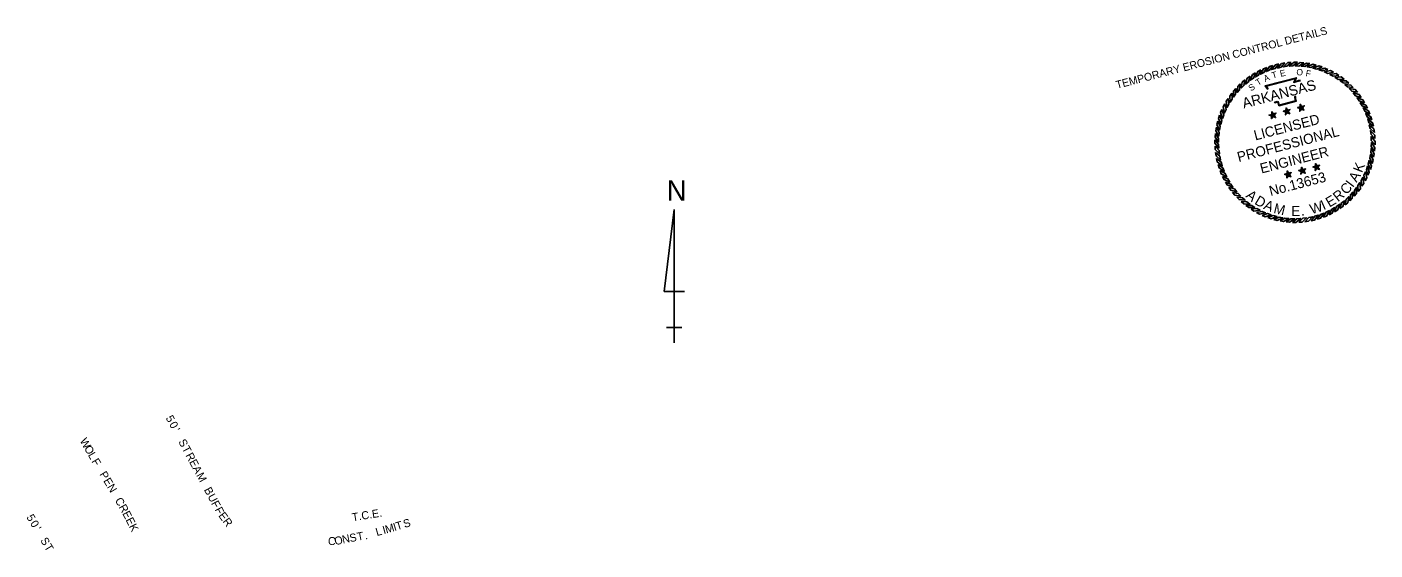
# Model space of a CAD drawing. Extents: x 830993 to 836451, y 495580 to 497751.
# Drawn here: x 835245 to 836255, y 496986 to 497378 of the extents above; entities that cross this region are included whole.
import ezdxf

# ---------------------------------------------------------------- set-up
doc = ezdxf.new("R2010")
doc.units = 0
for name, color, linetype in [('1', 7, 'Continuous'), ('8', 7, 'Continuous'), ('G-ANNO-STMP-AEW', 7, 'Continuous'), ('G-ANNO-TEXT', 7, 'Continuous'), ('Level 1', 7, 'Continuous'), ('R_Draft', 7, 'Continuous')]:
    doc.layers.add(name, color=color, linetype=linetype)

msp = doc.modelspace()

# ---------------------------------------------------------------- linework, layer by layer
at = {"layer": 'G-ANNO-STMP-AEW'}
for points in [[(836173.7, 497347.8), (836171.3, 497346.9), (836169.1, 497342.8), (836171.6, 497344)], [(836178.2, 497349.3), (836175.7, 497348.6), (836173.2, 497344.7), (836175.8, 497345.7)], [(836182.7, 497350.5), (836180.2, 497349.9), (836177.4, 497346.2), (836180.1, 497347)], [(836187.4, 497351.2), (836184.8, 497350.9), (836181.8, 497347.4), (836184.5, 497348)], [(836192.1, 497351.6), (836189.5, 497351.5), (836186.2, 497348.3), (836188.9, 497348.7)], [(836196.8, 497351.7), (836194.2, 497351.7), (836190.6, 497348.8), (836193.4, 497349)], [(836201.5, 497351.4), (836198.9, 497351.6), (836195.1, 497349), (836197.9, 497348.9)], [(836206.1, 497350.7), (836203.6, 497351.1), (836199.6, 497348.8), (836202.4, 497348.5)], [(836210.7, 497349.6), (836208.2, 497350.2), (836204.1, 497348.2), (836206.8, 497347.7)], [(836215.2, 497348.2), (836212.8, 497349), (836208.5, 497347.3), (836211.2, 497346.6)], [(836219.6, 497346.4), (836217.2, 497347.4), (836212.8, 497346.1), (836215.4, 497345.2)], [(836157.4, 497338.5), (836155.4, 497336.9), (836154.6, 497332.4), (836156.6, 497334.3)], [(836161.2, 497341.3), (836159.1, 497339.8), (836157.9, 497335.4), (836160.1, 497337.1)], [(836165.2, 497343.8), (836163, 497342.5), (836161.4, 497338.2), (836163.7, 497339.7)], [(836169.4, 497346), (836167, 497344.9), (836165.2, 497340.7), (836167.6, 497342)], [(836223.8, 497344.3), (836221.5, 497345.5), (836217, 497344.5), (836219.6, 497343.4)], [(836227.8, 497341.9), (836225.7, 497343.2), (836221.1, 497342.6), (836223.5, 497341.3)], [(836231.7, 497339.1), (836229.6, 497340.7), (836225, 497340.4), (836227.3, 497338.9)], [(836235.3, 497336.1), (836233.3, 497337.8), (836228.7, 497337.9), (836231, 497336.2)], [(836147.5, 497328.5), (836146, 497326.4), (836146.2, 497321.8), (836147.7, 497324.2)], [(836150.5, 497332.1), (836148.8, 497330.1), (836148.7, 497325.6), (836150.4, 497327.8)], [(836153.8, 497335.5), (836152, 497333.6), (836151.5, 497329.1), (836153.4, 497331.1)], [(836238.6, 497332.8), (836236.8, 497334.6), (836232.3, 497335.1), (836234.3, 497333.2)], [(836241.7, 497329.2), (836240.1, 497331.2), (836235.6, 497332), (836237.5, 497330)], [(836244.5, 497325.4), (836243, 497327.5), (836238.6, 497328.7), (836240.3, 497326.6)], [(836140.2, 497316.4), (836139.2, 497314), (836140.5, 497309.6), (836141.5, 497312.2)], [(836142.3, 497320.6), (836141.1, 497318.3), (836142.1, 497313.8), (836143.2, 497316.4)], [(836144.8, 497324.7), (836143.4, 497322.5), (836144, 497317.9), (836145.3, 497320.4)], [(836188.9, 497314.8), (836189.3, 497315.8), (836188.2, 497317.5), (836188.1, 497315.5)], [(836188.9, 497314.8), (836189.9, 497314.8), (836191.2, 497316.3), (836189.3, 497315.8)], [(836199.5, 497317.6), (836198.7, 497318.3), (836196.8, 497317.8), (836198.6, 497317)], [(836199.5, 497317.6), (836198.6, 497317), (836198.5, 497315), (836199.8, 497316.6)], [(836199.5, 497317.6), (836199.9, 497318.6), (836198.8, 497320.3), (836198.7, 497318.3)], [(836199.5, 497317.6), (836200.6, 497317.5), (836201.8, 497319.1), (836199.9, 497318.6)], [(836199.5, 497317.6), (836199.8, 497316.6), (836201.6, 497315.9), (836200.6, 497317.5)], [(836247, 497321.4), (836245.7, 497323.7), (836241.4, 497325.2), (836242.9, 497322.9)], [(836249.2, 497317.3), (836248, 497319.6), (836243.8, 497321.4), (836245.2, 497319)], [(836251, 497312.9), (836250.1, 497315.3), (836246, 497317.5), (836247.2, 497315)], [(836137, 497307.5), (836136.4, 497305), (836138.4, 497300.9), (836138.9, 497303.6)], [(836138.4, 497312), (836137.6, 497309.6), (836139.3, 497305.3), (836140, 497308)], [(836178.3, 497312.1), (836177.5, 497312.7), (836175.5, 497312.2), (836177.4, 497311.5)], [(836178.3, 497312.1), (836177.4, 497311.5), (836177.3, 497309.5), (836178.5, 497311.1)], [(836178.3, 497312.1), (836178.7, 497313.1), (836177.6, 497314.7), (836177.5, 497312.7)], [(836178.3, 497312.1), (836179.3, 497312), (836180.6, 497313.6), (836178.7, 497313.1)], [(836178.3, 497312.1), (836178.5, 497311.1), (836180.4, 497310.3), (836179.3, 497312)], [(836188.9, 497314.8), (836188.1, 497315.5), (836186.2, 497315), (836188, 497314.3)], [(836188.9, 497314.8), (836188, 497314.3), (836187.9, 497312.3), (836189.2, 497313.8)], [(836188.9, 497314.8), (836189.2, 497313.8), (836191, 497313.1), (836189.9, 497314.8)], [(836252.5, 497308.5), (836251.8, 497310.9), (836247.9, 497313.4), (836248.9, 497310.8)], [(836253.7, 497303.9), (836253.1, 497306.4), (836249.4, 497309.2), (836250.2, 497306.5)], [(836135.3, 497298.3), (836135, 497295.7), (836137.6, 497291.9), (836137.7, 497294.7)], [(836136, 497303), (836135.5, 497300.4), (836137.8, 497296.4), (836138.1, 497299.2)], [(836254.4, 497299.2), (836254.1, 497301.8), (836250.6, 497304.9), (836251.2, 497302.1)], [(836254.8, 497294.5), (836254.7, 497297.1), (836251.5, 497300.4), (836251.9, 497297.7)], [(836254.9, 497289.8), (836254.9, 497292.4), (836252, 497296), (836252.1, 497293.2)], [(836134.9, 497293.6), (836134.9, 497291), (836137.8, 497287.4), (836137.7, 497290.2)], [(836135, 497288.9), (836135.1, 497286.3), (836138.3, 497283), (836138, 497285.7)], [(836253.8, 497280.5), (836254.3, 497283), (836252, 497287), (836251.7, 497284.2)], [(836254.5, 497285.1), (836254.8, 497287.7), (836252.2, 497291.5), (836252.1, 497288.7)], [(836135.4, 497284.2), (836135.8, 497281.6), (836139.2, 497278.6), (836138.6, 497281.3)], [(836136.1, 497279.5), (836136.7, 497277), (836140.4, 497274.2), (836139.6, 497276.9)], [(836211.1, 497273.1), (836211.5, 497274.1), (836210.4, 497275.8), (836210.3, 497273.8)], [(836251.4, 497271.4), (836252.2, 497273.8), (836250.5, 497278.1), (836249.8, 497275.4)], [(836252.8, 497275.9), (836253.4, 497278.4), (836251.4, 497282.5), (836250.9, 497279.8)], [(836137.3, 497275), (836138.1, 497272.5), (836141.9, 497270), (836140.9, 497272.6)], [(836138.8, 497270.5), (836139.7, 497268.1), (836143.8, 497265.9), (836142.6, 497268.4)], [(836140.6, 497266.2), (836141.8, 497263.9), (836146, 497262), (836144.6, 497264.4)], [(836189.8, 497267.6), (836189, 497268.3), (836187.1, 497267.8), (836188.9, 497267)], [(836189.8, 497267.6), (836188.9, 497267), (836188.8, 497265.1), (836190.1, 497266.6)], [(836189.8, 497267.6), (836190.2, 497268.6), (836189.1, 497270.3), (836189, 497268.3)], [(836189.8, 497267.6), (836190.9, 497267.5), (836192.1, 497269.1), (836190.2, 497268.6)], [(836189.8, 497267.6), (836190.1, 497266.6), (836191.9, 497265.9), (836190.9, 497267.5)], [(836200.4, 497270.4), (836199.6, 497271), (836197.7, 497270.5), (836199.6, 497269.8)], [(836200.4, 497270.4), (836199.6, 497269.8), (836199.4, 497267.8), (836200.7, 497269.4)], [(836200.4, 497270.4), (836200.8, 497271.3), (836199.8, 497273), (836199.6, 497271)], [(836200.4, 497270.4), (836201.5, 497270.3), (836202.8, 497271.8), (836200.8, 497271.3)], [(836200.4, 497270.4), (836200.7, 497269.4), (836202.6, 497268.6), (836201.5, 497270.3)], [(836211.1, 497273.1), (836210.3, 497273.8), (836208.3, 497273.3), (836210.2, 497272.6)], [(836211.1, 497273.1), (836210.2, 497272.6), (836210.1, 497270.6), (836211.3, 497272.1)], [(836211.1, 497273.1), (836212.1, 497273.1), (836213.4, 497274.6), (836211.5, 497274.1)], [(836211.1, 497273.1), (836211.3, 497272.1), (836213.2, 497271.4), (836212.1, 497273.1)], [(836247.5, 497262.8), (836248.7, 497265.1), (836247.7, 497269.6), (836246.6, 497267)], [(836249.6, 497267), (836250.6, 497269.4), (836249.3, 497273.8), (836248.4, 497271.2)], [(836142.8, 497262), (836144.1, 497259.8), (836148.4, 497258.2), (836146.9, 497260.5)], [(836145.3, 497258), (836146.8, 497255.9), (836151.2, 497254.7), (836149.5, 497256.9)], [(836239.3, 497251.3), (836241, 497253.3), (836241.1, 497257.9), (836239.4, 497255.7)], [(836242.3, 497254.9), (836243.9, 497257), (836243.6, 497261.6), (836242.1, 497259.3)], [(836245.1, 497258.8), (836246.4, 497261), (836245.8, 497265.5), (836244.5, 497263.1)], [(836148.1, 497254.2), (836149.7, 497252.2), (836154.3, 497251.4), (836152.3, 497253.4)], [(836151.2, 497250.6), (836153, 497248.8), (836157.5, 497248.3), (836155.5, 497250.2)], [(836154.5, 497247.3), (836156.5, 497245.6), (836161.1, 497245.5), (836158.9, 497247.2)], [(836228.6, 497242.1), (836230.7, 497243.6), (836231.9, 497248), (836229.8, 497246.3)], [(836232.4, 497244.9), (836234.4, 497246.5), (836235.2, 497251.1), (836233.2, 497249.1)], [(836236, 497248), (836237.8, 497249.8), (836238.3, 497254.4), (836236.4, 497252.3)], [(836158.1, 497244.3), (836160.2, 497242.8), (836164.8, 497243), (836162.5, 497244.5)], [(836162, 497241.6), (836164.1, 497240.2), (836168.7, 497240.8), (836166.3, 497242.1)], [(836166, 497239.1), (836168.3, 497237.9), (836172.8, 497238.9), (836170.2, 497240)], [(836170.2, 497237), (836172.6, 497236), (836177, 497237.3), (836174.4, 497238.3)], [(836174.6, 497235.3), (836177, 497234.4), (836181.3, 497236.1), (836178.6, 497236.8)], [(836179.1, 497233.8), (836181.6, 497233.2), (836185.7, 497235.2), (836183, 497235.7)], [(836202.4, 497232.2), (836205, 497232.6), (836208.1, 497236), (836205.3, 497235.4)], [(836207.1, 497233), (836209.6, 497233.5), (836212.4, 497237.2), (836209.7, 497236.4)], [(836211.6, 497234.1), (836214.1, 497234.9), (836216.6, 497238.7), (836214, 497237.7)], [(836216.1, 497235.6), (836218.5, 497236.5), (836220.7, 497240.6), (836218.2, 497239.4)], [(836220.5, 497237.4), (836222.8, 497238.6), (836224.6, 497242.8), (836222.2, 497241.4)], [(836224.6, 497239.6), (836226.8, 497240.9), (836228.4, 497245.3), (836226.1, 497243.7)], [(836183.7, 497232.8), (836186.2, 497232.3), (836190.2, 497234.6), (836187.4, 497234.9)], [(836188.3, 497232.1), (836190.9, 497231.8), (836194.7, 497234.5), (836191.9, 497234.5)], [(836193, 497231.7), (836195.6, 497231.7), (836199.2, 497234.6), (836196.4, 497234.5)], [(836197.7, 497231.8), (836200.3, 497232), (836203.6, 497235.1), (836200.9, 497234.8)]]:
    msp.add_lwpolyline(points, close=True, dxfattribs=at)
for points in [[(836174.6, 497331.4), (836172.5, 497334), (836196, 497340.1), (836194.6, 497337.2), (836196.2, 497337.6), (836197.5, 497338), (836198.9, 497338.2)], [(836174.9, 497331.7), (836173.2, 497333.8), (836195.3, 497339.6), (836194, 497336.6), (836196.3, 497337.2), (836197.6, 497337.6), (836199, 497337.8)], [(836195.6, 497326.4), (836195.3, 497326), (836195.3, 497325.5), (836195.4, 497324.2), (836195.9, 497322.6), (836182.8, 497319.2), (836182.2, 497321.4), (836182.1, 497321.9), (836181.5, 497321.9), (836179.7, 497321.4), (836179.2, 497321.8)], [(836195.3, 497326.6), (836194.9, 497326.1), (836194.9, 497325.4), (836195.1, 497324.1), (836195.4, 497322.9), (836183.1, 497319.7), (836182.6, 497321.5), (836182.4, 497322.2), (836181.5, 497322.3), (836179.8, 497321.8), (836179.5, 497322.1)]]:
    msp.add_lwpolyline(points, dxfattribs=at)
at = {"layer": 'Level 1'}
for p, q in [((835729.7, 497241.5), (835722, 497179.9)), ((835729.7, 497141.5), (835729.7, 497241.5)), ((835729.7, 497241.5), (835729.7, 497164.5)), ((835722, 497179.9), (835737.4, 497179.9)), ((835729.7, 497141.5), (835729.7, 497164.5)), ((835729.7, 497153), (835723.9, 497153)), ((835723.9, 497153), (835735.4, 497153)), ((835729.7, 497141.5), (835729.7, 497153))]:
    msp.add_line(p, q, dxfattribs=at)

# ---------------------------------------------------------------- texts
at = {"layer": '1'}
msp.add_text('TEMPORARY EROSION CONTROL DETAILS', height=5.862, rotation=14.5644, dxfattribs=at).set_placement((836061.5, 497331.8))
at = {"layer": '8'}
for s, rotation, p in [('5', 298.0637, (835348.3, 497085.2)), ('0', 298.0637, (835350.9, 497080.5)), ("'", 298.0637, (835353.6, 497075.3)), ('S', 298.0637, (835357.8, 497067.4)), ('T', 298.0637, (835360.5, 497062.4)), ('R', 298.0637, (835363.2, 497057.2)), ('E', 298.0637, (835365.9, 497052.2)), ('A', 298.0637, (835368.4, 497047.5)), ('M', 298.0637, (835371.2, 497042.3)), ('B', 298.0637, (835377, 497031.4)), ('U', 298.0637, (835379.7, 497026.4)), ('F', 298.0637, (835382.4, 497021.3)), ('5', 301.0659, (835243.9, 497010.8)), ('F', 298.0637, (835385, 497016.5)), ('E', 306.2875, (835387.7, 497011.9)), ('T.C.E.', 9.2892, (835488.6, 497007.7)), ('0', 301.0659, (835246.6, 497006.2)), ("'", 301.0659, (835249.7, 497001.1)), ('R', 306.2875, (835390.9, 497007.6)), ('S', 301.0659, (835254.3, 496993.5)), ('T', 301.0659, (835257.2, 496988.6))]:
    msp.add_text(s, height=6, rotation=rotation, dxfattribs=at).set_placement(p)
at = {"layer": 'G-ANNO-TEXT'}
for s, height, rotation, p in [('O', 4.77, 355.7862, (836195.8, 497342.1)), ('ARKANSAS', 7.79, 14.5644, (836156.5, 497317.1)), ('T', 4.77, 31.4658, (836167.2, 497334)), ('A', 4.77, 23.2431, (836172.5, 497336.9)), ('T', 4.77, 16.0432, (836178.2, 497339.4)), ('E', 4.77, 11.2364, (836184.1, 497340.8)), ('F', 4.77, 349.9272, (836202.6, 497341.3)), ('S', 4.77, 34.3369, (836162, 497329.8)), ('LICENSED', 7.54, 14.5644, (836165.2, 497293.1)), ('PROFESSIONAL', 7.543, 14.5644, (836152.7, 497276.9)), ('ENGINEER', 7.54, 14.5644, (836169.8, 497268.3)), ('K', 7.54, 68.4114, (836245.1, 497268.5)), ('No.13653', 7.51, 14.5644, (836176.6, 497251.5)), ('A', 7.54, 59.7493, (836241.1, 497261.3)), ('R', 7.54, 38.726, (836227.1, 497246.8)), ('C', 7.54, 46.704, (836233.4, 497252)), ('I', 7.54, 52.9701, (836238.2, 497257.4)), ('A', 7.54, 320.5464, (836157.5, 497251)), ('D', 7.54, 328.8665, (836164, 497245.9)), ('A', 7.54, 337.1867, (836170.8, 497242)), ('M', 7.54, 346.3612, (836178.4, 497238.9)), ('W', 7.54, 16.6771, (836207.3, 497237.8)), ('I', 7.54, 24.1397, (836216.3, 497240.8)), ('E', 7.54, 30.5769, (836220.7, 497242.8)), ('E', 7.54, 359.8426, (836192.1, 497236.5)), ('.', 7.54, 5.4227, (836199.6, 497236.7))]:
    msp.add_text(s, height=height, rotation=rotation, dxfattribs=at).set_placement(p)
at = {"layer": 'Level 1'}
msp.add_text('N', height=15.4, rotation=360, dxfattribs=at).set_placement((835724, 497247.9))
at = {"layer": 'R_Draft'}
for s, rotation, p in [('W', 299.5944, (835283.9, 497068.1)), ('O', 299.8641, (835287.1, 497062.5)), ('L', 300.2411, (835290, 497057.4)), ('F', 300.6913, (835292.7, 497052.7)), ('P', 301.2077, (835298.6, 497043)), ('E', 301.1388, (835301.5, 497038.1)), ('N', 300.8693, (835304.3, 497033.5)), ('C', 299.5902, (835310.2, 497023.5)), ('R', 298.6275, (835313.1, 497018.5)), ('E', 297.7536, (835315.8, 497013.6)), ('E', 297.1516, (835318.3, 497008.8)), ('K', 296.7686, (835320.7, 497004)), ('I', 15.9908, (835512, 496998.1)), ('M', 15.9908, (835513.9, 496998.6)), ('I', 16.6265, (835520, 497000.4)), ('T', 16.6265, (835521.9, 497001)), ('S', 16.6265, (835527.5, 497002.7)), ('C', 355.4611, (835469.9, 496990.2)), ('O', 12.2017, (835475.6, 496989.8)), ('N', 11.342, (835481.3, 496991.1)), ('S', 10.4973, (835486.8, 496992.1)), ('T', 10.4973, (835492.4, 496993.2)), ('.', 17.8928, (835498.2, 496994)), ('L', 15.9908, (835506.8, 496996.6))]:
    msp.add_text(s, height=6, rotation=rotation, dxfattribs=at).set_placement(p)

doc.saveas('drawing.dxf')
